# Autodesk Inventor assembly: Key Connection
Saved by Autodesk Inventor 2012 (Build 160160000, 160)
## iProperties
Created: 2011-01
Part Number: Key Connection
Document SubType Name: Assembly
Designer: Beta-8540w
ClientObjectVersion: 1
Author: Beta-8540w
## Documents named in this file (2)
- C:\Users\VMuser\Desktop\Inventor 2012 Essentials\Assemblies\Chapter 8\Design Accelerators\Key Connection c8-01.iam
- C:\Users\VMuser\Desktop\Inventor 2012 Essentials\Content Center Files\en-US\DIN 6885  A\DIN 6885 - A 4 x 4 x 12.ipt
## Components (1 placed, 1 different names)
1. DIN 6885 A A 4 x 4 x 12:1
